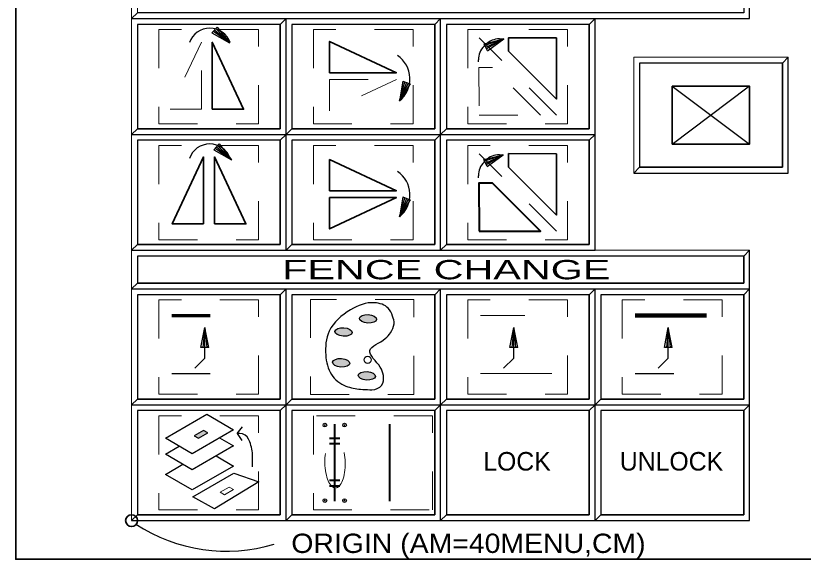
# Model space of a CAD drawing. Extents: x 95906.8 to 95923.6, y 90964.8 to 90972.8.
# Drawn here: x 95906.832 to 95908.871, y 90964.762 to 90966.169 of the extents above; entities that cross this region are included whole.
import ezdxf
from ezdxf.enums import TextEntityAlignment as Align

# ---------------------------------------------------------------- set-up
doc = ezdxf.new("R2010")
doc.units = 0
doc.header["$LTSCALE"] = 0.019
doc.header["$PDMODE"] = 32
doc.header["$PDSIZE"] = 0.0095
for name, pattern in [('DOT_DASHED', [7.7, 5, -1.2, 0.3, -1.2]), ('DOTTED', [1.5, 0.3, -1.2]), ('LONG_DASHED', [7.5, 6, -1.5]), ('MEDIUM_DASHED', [4.5, 3, -1.5])]:
    doc.linetypes.add(name, pattern=pattern)
for name, color, linetype, lineweight in [('11', 7, 'Continuous', 25), ('12', 7, 'Continuous', 25), ('16', 7, 'Continuous', 25), ('18', 7, 'Continuous', 25), ('2', 7, 'Continuous', 13), ('3', 7, 'Continuous', 25), ('6', 7, 'Continuous', 25), ('7', 7, 'Continuous', 35)]:
    doc.layers.add(name, color=color, linetype=linetype, lineweight=lineweight)

msp = doc.modelspace()

# ---------------------------------------------------------------- hatches: boundary and pattern name
at = {"layer": '6'}
h = msp.add_hatch(color=256, dxfattribs=at)
edge = h.paths.add_edge_path()
edge.add_ellipse((95907.7443, 90965.3842), major_axis=(-0.0223, 0.0015), ratio=0.490241, start_angle=0, end_angle=360)
h = msp.add_hatch(color=256, dxfattribs=at)
edge = h.paths.add_edge_path()
edge.add_ellipse((95907.6812, 90965.3504), major_axis=(-0.0223, 0.0015), ratio=0.490241, start_angle=0, end_angle=360)
h = msp.add_hatch(color=256, dxfattribs=at)
edge = h.paths.add_edge_path()
edge.add_ellipse((95907.6751, 90965.2705), major_axis=(-0.0223, 0.0015), ratio=0.490241, start_angle=0, end_angle=360)
h = msp.add_hatch(color=256, dxfattribs=at)
edge = h.paths.add_edge_path()
edge.add_ellipse((95907.7412, 90965.2366), major_axis=(-0.0223, 0.0015), ratio=0.490241, start_angle=0, end_angle=360)
msp.add_hatch(color=256, dxfattribs=at).paths.add_polyline_path([(95907.3058, 90965.0753), (95907.3293, 90965.0889), (95907.3181, 90965.0953), (95907.2946, 90965.0817)])

# ---------------------------------------------------------------- linework, layer by layer
at = {"layer": '11'}
for points in [[(95907.5473, 90965.8767), (95907.9173, 90965.8767), (95907.9173, 90966.1467), (95907.5473, 90966.1467)], [(95907.9473, 90965.8767), (95908.3173, 90965.8767), (95908.3173, 90966.1467), (95907.9473, 90966.1467)], [(95907.1473, 90965.5767), (95907.5173, 90965.5767), (95907.5173, 90965.8467), (95907.1473, 90965.8467)], [(95907.5473, 90965.5767), (95907.9173, 90965.5767), (95907.9173, 90965.8467), (95907.5473, 90965.8467)], [(95907.9473, 90965.5767), (95908.3173, 90965.5767), (95908.3173, 90965.8467), (95907.9473, 90965.8467)], [(95907.1473, 90965.1767), (95907.5173, 90965.1767), (95907.5173, 90965.4467), (95907.1473, 90965.4467)], [(95907.5473, 90965.1767), (95907.9173, 90965.1767), (95907.9173, 90965.4467), (95907.5473, 90965.4467)], [(95907.9473, 90965.1767), (95908.3173, 90965.1767), (95908.3173, 90965.4467), (95907.9473, 90965.4467)], [(95907.1473, 90964.8767), (95907.5173, 90964.8767), (95907.5173, 90965.1467), (95907.1473, 90965.1467)], [(95907.5473, 90964.8767), (95907.9173, 90964.8767), (95907.9173, 90965.1467), (95907.5473, 90965.1467)], [(95907.9473, 90964.8767), (95908.3173, 90964.8767), (95908.3173, 90965.1467), (95907.9473, 90965.1467)], [(95908.3473, 90964.8767), (95908.7173, 90964.8767), (95908.7173, 90965.1467), (95908.3473, 90965.1467)]]:
    msp.add_lwpolyline(points, close=True, dxfattribs=at)
at = {"layer": '12'}
for points in [[(95907.1473, 90965.8767), (95907.5173, 90965.8767), (95907.5173, 90966.1467), (95907.1473, 90966.1467)], [(95908.3473, 90965.1767), (95908.7173, 90965.1767), (95908.7173, 90965.4467), (95908.3473, 90965.4467)]]:
    msp.add_lwpolyline(points, close=True, dxfattribs=at)
at = {"layer": '16'}
msp.add_lwpolyline([(95908.4473, 90965.7767), (95908.8173, 90965.7767), (95908.8173, 90966.0467), (95908.4473, 90966.0467)], close=True, dxfattribs=at)
at = {"layer": '18'}
msp.add_lwpolyline([(95907.1473, 90965.4767), (95908.7173, 90965.4767), (95908.7173, 90965.5467), (95907.1473, 90965.5467)], close=True, dxfattribs=at)
at = {"layer": '2'}
for points in [[(95907.1323, 90966.2617), (95907.1323, 90966.1617), (95907.1473, 90966.1767), (95907.1473, 90966.2467), (95908.7173, 90966.2467), (95908.7323, 90966.2617)], [(95907.1323, 90966.1617), (95907.1323, 90965.8617), (95907.1473, 90965.8767), (95907.1473, 90966.1467), (95907.5173, 90966.1467), (95907.5323, 90966.1617)], [(95907.5323, 90966.1617), (95907.5323, 90965.8617), (95907.5473, 90965.8767), (95907.5473, 90966.1467), (95907.9173, 90966.1467), (95907.9323, 90966.1617)], [(95907.9323, 90966.1617), (95907.9323, 90965.8617), (95907.9473, 90965.8767), (95907.9473, 90966.1467), (95908.3173, 90966.1467), (95908.3323, 90966.1617)], [(95908.4323, 90966.0617), (95908.4323, 90965.7617), (95908.4473, 90965.7767), (95908.4473, 90966.0467), (95908.8173, 90966.0467), (95908.8323, 90966.0617)], [(95907.1323, 90965.8617), (95907.1323, 90965.5617), (95907.1473, 90965.5767), (95907.1473, 90965.8467), (95907.5173, 90965.8467), (95907.5323, 90965.8617)], [(95907.5323, 90965.8617), (95907.5323, 90965.5617), (95907.5473, 90965.5767), (95907.5473, 90965.8467), (95907.9173, 90965.8467), (95907.9323, 90965.8617)], [(95907.9323, 90965.8617), (95907.9323, 90965.5617), (95907.9473, 90965.5767), (95907.9473, 90965.8467), (95908.3173, 90965.8467), (95908.3323, 90965.8617)], [(95907.1323, 90965.5617), (95907.1323, 90965.4617), (95907.1473, 90965.4767), (95907.1473, 90965.5467), (95908.7173, 90965.5467), (95908.7323, 90965.5617)], [(95907.1323, 90965.4617), (95907.1323, 90965.1617), (95907.1473, 90965.1767), (95907.1473, 90965.4467), (95907.5173, 90965.4467), (95907.5323, 90965.4617)], [(95907.5323, 90965.4617), (95907.5323, 90965.1617), (95907.5473, 90965.1767), (95907.5473, 90965.4467), (95907.9173, 90965.4467), (95907.9323, 90965.4617)], [(95907.9323, 90965.4617), (95907.9323, 90965.1617), (95907.9473, 90965.1767), (95907.9473, 90965.4467), (95908.3173, 90965.4467), (95908.3323, 90965.4617)], [(95908.3323, 90965.4617), (95908.3323, 90965.1617), (95908.3473, 90965.1767), (95908.3473, 90965.4467), (95908.7173, 90965.4467), (95908.7323, 90965.4617)], [(95907.1323, 90965.1617), (95907.1323, 90964.8617), (95907.1473, 90964.8767), (95907.1473, 90965.1467), (95907.5173, 90965.1467), (95907.5323, 90965.1617)], [(95907.5323, 90965.1617), (95907.5323, 90964.8617), (95907.5473, 90964.8767), (95907.5473, 90965.1467), (95907.9173, 90965.1467), (95907.9323, 90965.1617)], [(95907.9323, 90965.1617), (95907.9323, 90964.8617), (95907.9473, 90964.8767), (95907.9473, 90965.1467), (95908.3173, 90965.1467), (95908.3323, 90965.1617)], [(95908.3323, 90965.1617), (95908.3323, 90964.8617), (95908.3473, 90964.8767), (95908.3473, 90965.1467), (95908.7173, 90965.1467), (95908.7323, 90965.1617)]]:
    msp.add_lwpolyline(points, close=True, dxfattribs=at)
at = {"layer": '3'}
for points in [[(95907.1323, 90966.1617), (95908.7323, 90966.1617), (95908.7323, 90966.2617), (95908.7173, 90966.2467), (95908.7173, 90966.1767), (95907.1473, 90966.1767)], [(95907.1323, 90965.8617), (95907.5323, 90965.8617), (95907.5323, 90966.1617), (95907.5173, 90966.1467), (95907.5173, 90965.8767), (95907.1473, 90965.8767)], [(95907.5323, 90965.8617), (95907.9323, 90965.8617), (95907.9323, 90966.1617), (95907.9173, 90966.1467), (95907.9173, 90965.8767), (95907.5473, 90965.8767)], [(95907.9323, 90965.8617), (95908.3323, 90965.8617), (95908.3323, 90966.1617), (95908.3173, 90966.1467), (95908.3173, 90965.8767), (95907.9473, 90965.8767)], [(95908.4323, 90965.7617), (95908.8323, 90965.7617), (95908.8323, 90966.0617), (95908.8173, 90966.0467), (95908.8173, 90965.7767), (95908.4473, 90965.7767)], [(95907.1323, 90965.5617), (95907.5323, 90965.5617), (95907.5323, 90965.8617), (95907.5173, 90965.8467), (95907.5173, 90965.5767), (95907.1473, 90965.5767)], [(95907.5323, 90965.5617), (95907.9323, 90965.5617), (95907.9323, 90965.8617), (95907.9173, 90965.8467), (95907.9173, 90965.5767), (95907.5473, 90965.5767)], [(95907.9323, 90965.5617), (95908.3323, 90965.5617), (95908.3323, 90965.8617), (95908.3173, 90965.8467), (95908.3173, 90965.5767), (95907.9473, 90965.5767)], [(95907.1323, 90965.4617), (95908.7323, 90965.4617), (95908.7323, 90965.5617), (95908.7173, 90965.5467), (95908.7173, 90965.4767), (95907.1473, 90965.4767)], [(95907.1323, 90965.1617), (95907.5323, 90965.1617), (95907.5323, 90965.4617), (95907.5173, 90965.4467), (95907.5173, 90965.1767), (95907.1473, 90965.1767)], [(95907.5323, 90965.1617), (95907.9323, 90965.1617), (95907.9323, 90965.4617), (95907.9173, 90965.4467), (95907.9173, 90965.1767), (95907.5473, 90965.1767)], [(95907.9323, 90965.1617), (95908.3323, 90965.1617), (95908.3323, 90965.4617), (95908.3173, 90965.4467), (95908.3173, 90965.1767), (95907.9473, 90965.1767)], [(95908.3323, 90965.1617), (95908.7323, 90965.1617), (95908.7323, 90965.4617), (95908.7173, 90965.4467), (95908.7173, 90965.1767), (95908.3473, 90965.1767)], [(95907.1323, 90964.8617), (95907.5323, 90964.8617), (95907.5323, 90965.1617), (95907.5173, 90965.1467), (95907.5173, 90964.8767), (95907.1473, 90964.8767)], [(95907.5323, 90964.8617), (95907.9323, 90964.8617), (95907.9323, 90965.1617), (95907.9173, 90965.1467), (95907.9173, 90964.8767), (95907.5473, 90964.8767)], [(95907.9323, 90964.8617), (95908.3323, 90964.8617), (95908.3323, 90965.1617), (95908.3173, 90965.1467), (95908.3173, 90964.8767), (95907.9473, 90964.8767)], [(95908.3323, 90964.8617), (95908.7323, 90964.8617), (95908.7323, 90965.1617), (95908.7173, 90965.1467), (95908.7173, 90964.8767), (95908.3473, 90964.8767)]]:
    msp.add_lwpolyline(points, close=True, dxfattribs=at)
at = {"layer": '6'}
for p, q in [((95907.3858, 90966.099), (95907.3439, 90966.1287)), ((95907.3469, 90966.1323), (95907.3858, 90966.099)), ((95908.0494, 90966.0876), (95908.0958, 90966.1092)), ((95908.0958, 90966.1092), (95908.0514, 90966.0832)), ((95908.0846, 90966.1094), (95908.0947, 90966.1094)), ((95908.0447, 90966.0902), (95908.0493, 90966.0948)), ((95908.0301, 90966.0495), (95908.0301, 90966.0549)), ((95907.8257, 90965.9486), (95907.84, 90965.998)), ((95907.8444, 90965.9962), (95907.8257, 90965.9486)), ((95908.5323, 90965.9867), (95908.7323, 90965.8367)), ((95908.5323, 90965.8367), (95908.7287, 90965.9852)), ((95907.3908, 90965.7961), (95907.3488, 90965.8258)), ((95907.3519, 90965.8294), (95907.3908, 90965.7961)), ((95908.0447, 90965.7902), (95908.0493, 90965.7948)), ((95908.0483, 90965.7878), (95908.0947, 90965.8094)), ((95908.0947, 90965.8094), (95908.0503, 90965.7834)), ((95908.0846, 90965.8094), (95908.0947, 90965.8094)), ((95908.0301, 90965.7495), (95908.0301, 90965.7549)), ((95907.8257, 90965.6486), (95907.84, 90965.698)), ((95907.8444, 90965.6962), (95907.8257, 90965.6486)), ((95907.3219, 90965.3105), (95907.3219, 90965.3617)), ((95907.3219, 90965.3617), (95907.3267, 90965.3105)), ((95908.1219, 90965.3105), (95908.1219, 90965.3617)), ((95908.1219, 90965.3617), (95908.1267, 90965.3105)), ((95908.5219, 90965.3105), (95908.5219, 90965.3617)), ((95908.5219, 90965.3617), (95908.5267, 90965.3105)), ((95907.4057, 90965.0875), (95907.4196, 90965.1044)), ((95907.4057, 90965.0875), (95907.418, 90965.0691)), ((95907.4124, 90965.0875), (95907.4057, 90965.0875)), ((95907.438, 90965.0659), (95907.4353, 90965.0725)), ((95907.4457, 90965.0014), (95907.4457, 90965.0275)), ((95907.4457, 90965.0014), (95907.4457, 90965.0275))]:
    msp.add_line(p, q, dxfattribs=at)
at = {"layer": '6', "linetype": 'MEDIUM_DASHED', "lineweight": 13}
for p, q in [((95908.2323, 90965.9117), (95908.0323, 90966.1117)), ((95908.2323, 90965.6117), (95908.0323, 90965.8117))]:
    msp.add_line(p, q, dxfattribs=at)
at = {"layer": '6', "linetype": 'DOT_DASHED', "lineweight": 70}
msp.add_line((95907.2361, 90965.393), (95907.4205, 90965.393), dxfattribs=at)
at = {"layer": '6', "linetype": 'LONG_DASHED', "lineweight": 13}
msp.add_line((95908.0361, 90965.393), (95908.2205, 90965.393), dxfattribs=at)
at = {"layer": '6', "lineweight": 158}
msp.add_line((95908.4361, 90965.393), (95908.6205, 90965.393), dxfattribs=at)
at = {"layer": '6', "linetype": 'DOTTED'}
msp.add_line((95907.2361, 90965.2424), (95907.4205, 90965.2424), dxfattribs=at)
at = {"layer": '6', "lineweight": 13}
msp.add_line((95908.0361, 90965.2424), (95908.2205, 90965.2424), dxfattribs=at)
at = {"layer": '6', "linetype": 'MEDIUM_DASHED'}
msp.add_line((95908.4361, 90965.2424), (95908.6205, 90965.2424), dxfattribs=at)
at = {"layer": '6', "lineweight": 40}
for p, q in [((95907.6573, 90965.1117), (95907.6573, 90964.9117)), ((95907.8003, 90965.1117), (95907.8003, 90964.9117)), ((95907.6451, 90965.0752), (95907.6713, 90965.0752)), ((95907.6451, 90965.0614), (95907.6713, 90965.0614)), ((95907.6451, 90964.9661), (95907.6713, 90964.9661)), ((95907.6451, 90964.9522), (95907.6713, 90964.9522))]:
    msp.add_line(p, q, dxfattribs=at)
at = {"layer": '6'}
for points in [[(95907.3403, 90966.1246), (95907.3536, 90966.14), (95907.3858, 90966.099)], [(95907.3403, 90966.1246), (95907.3858, 90966.099), (95907.3503, 90966.1361)], [(95908.0537, 90966.0784), (95908.045, 90966.0968), (95908.0958, 90966.1092)], [(95908.0537, 90966.0784), (95908.0958, 90966.1092), (95908.0472, 90966.0921)], [(95907.8349, 90966), (95907.8539, 90965.9925), (95907.8257, 90965.9486)], [(95907.8349, 90966), (95907.8257, 90965.9486), (95907.8491, 90965.9944)], [(95907.3452, 90965.8216), (95907.3586, 90965.8372), (95907.3908, 90965.7961)], [(95907.3452, 90965.8216), (95907.3908, 90965.7961), (95907.3551, 90965.8332)], [(95908.0526, 90965.7785), (95908.044, 90965.797), (95908.0947, 90965.8094)], [(95908.0526, 90965.7785), (95908.0947, 90965.8094), (95908.0462, 90965.7923)], [(95907.8349, 90965.7), (95907.8539, 90965.6925), (95907.8257, 90965.6486)], [(95907.8349, 90965.7), (95907.8257, 90965.6486), (95907.8491, 90965.6944)], [(95907.2956, 90965.2564), (95907.3219, 90965.2827), (95907.3219, 90965.3617)], [(95907.3321, 90965.3105), (95907.3117, 90965.3105), (95907.3219, 90965.3617)], [(95907.3321, 90965.3105), (95907.3219, 90965.3617), (95907.3169, 90965.3105)], [(95908.0956, 90965.2564), (95908.1219, 90965.2827), (95908.1219, 90965.3617)], [(95908.1321, 90965.3105), (95908.1117, 90965.3105), (95908.1219, 90965.3617)], [(95908.1321, 90965.3105), (95908.1219, 90965.3617), (95908.1169, 90965.3105)], [(95908.4956, 90965.2564), (95908.5219, 90965.2827), (95908.5219, 90965.3617)], [(95908.5321, 90965.3105), (95908.5117, 90965.3105), (95908.5219, 90965.3617)], [(95908.5321, 90965.3105), (95908.5219, 90965.3617), (95908.5169, 90965.3105)], [(95907.3602, 90965.0763), (95907.3965, 90965.0552), (95907.2895, 90964.9934), (95907.2197, 90965.0337), (95907.2554, 90965.0543)], [(95907.3511, 90965.0292), (95907.3965, 90965.0029), (95907.2895, 90964.9411), (95907.2197, 90964.9814), (95907.265, 90965.0076)]]:
    msp.add_lwpolyline(points, dxfattribs=at)
at = {"layer": '6', "linetype": 'DOTTED', "lineweight": 13}
for points in [[(95907.2029, 90965.8893), (95907.4611, 90965.8893), (95907.4611, 90966.1332), (95907.2029, 90966.1332)], [(95907.6029, 90965.8893), (95907.8611, 90965.8893), (95907.8611, 90966.1332), (95907.6029, 90966.1332)], [(95908.0029, 90965.8893), (95908.2611, 90965.8893), (95908.2611, 90966.1332), (95908.0029, 90966.1332)], [(95907.2029, 90965.5893), (95907.4611, 90965.5893), (95907.4611, 90965.8332), (95907.2029, 90965.8332)], [(95907.6029, 90965.5893), (95907.8611, 90965.5893), (95907.8611, 90965.8332), (95907.6029, 90965.8332)], [(95908.0029, 90965.5893), (95908.2611, 90965.5893), (95908.2611, 90965.8332), (95908.0029, 90965.8332)], [(95907.2029, 90965.1893), (95907.4611, 90965.1893), (95907.4611, 90965.4332), (95907.2029, 90965.4332)], [(95907.8627, 90965.4347), (95907.5955, 90965.4347), (95907.5955, 90965.1883), (95907.8627, 90965.1883)], [(95908.0029, 90965.1893), (95908.2611, 90965.1893), (95908.2611, 90965.4332), (95908.0029, 90965.4332)], [(95908.4029, 90965.1893), (95908.6611, 90965.1893), (95908.6611, 90965.4332), (95908.4029, 90965.4332)], [(95907.2029, 90964.8893), (95907.4611, 90964.8893), (95907.4611, 90965.1332), (95907.2029, 90965.1332)], [(95907.6029, 90964.8893), (95907.9111, 90964.8893), (95907.9111, 90965.1332), (95907.6029, 90965.1332)]]:
    msp.add_lwpolyline(points, close=True, dxfattribs=at)
at = {"layer": '6', "linetype": 'MEDIUM_DASHED', "lineweight": 13}
for points in [[(95907.3129, 90965.9271), (95907.3129, 90966.1005), (95907.2318, 90965.9271)], [(95908.0323, 90965.9117), (95908.1909, 90965.9117), (95908.067, 90966.0356), (95908.0317, 90966.0356)], [(95907.6447, 90966.004), (95907.818, 90966.004), (95907.6447, 90965.9228)], [(95907.3724, 90964.9288), (95907.3959, 90964.9424), (95907.3847, 90964.9488), (95907.3612, 90964.9352)]]:
    msp.add_lwpolyline(points, close=True, dxfattribs=at)
at = {"layer": '6', "lineweight": 35}
for points in [[(95907.3412, 90965.9271), (95907.3412, 90966.1005), (95907.4224, 90965.9271)], [(95907.6447, 90966.0216), (95907.818, 90966.0216), (95907.6447, 90966.1027)], [(95908.2324, 90966.1118), (95908.2324, 90965.9532), (95908.1085, 90966.0771), (95908.1085, 90966.1124)], [(95908.5323, 90965.8367), (95908.7323, 90965.8367), (95908.7323, 90965.9867), (95908.5323, 90965.9867)], [(95908.2324, 90965.8118), (95908.2324, 90965.6532), (95908.1085, 90965.7771), (95908.1085, 90965.8124)], [(95907.3187, 90965.6303), (95907.3187, 90965.8037), (95907.2376, 90965.6303)], [(95907.347, 90965.6303), (95907.347, 90965.8037), (95907.4282, 90965.6303)], [(95907.6447, 90965.7158), (95907.818, 90965.7158), (95907.6447, 90965.7969)], [(95907.6447, 90965.6982), (95907.818, 90965.6982), (95907.6447, 90965.617)]]:
    msp.add_lwpolyline(points, close=True, dxfattribs=at)
at = {"layer": '6', "lineweight": 40}
msp.add_lwpolyline([(95908.0323, 90965.6117), (95908.1909, 90965.6117), (95908.067, 90965.7356), (95908.0317, 90965.7356)], close=True, dxfattribs=at)
at = {"layer": '6'}
for points in [[(95907.2197, 90965.0752), (95907.3267, 90965.137), (95907.3965, 90965.0967), (95907.2895, 90965.0349)], [(95907.3058, 90965.0753), (95907.3293, 90965.0889), (95907.3181, 90965.0953), (95907.2946, 90965.0817)], [(95907.2904, 90964.923), (95907.3974, 90964.9848), (95907.4617, 90964.9625), (95907.3468, 90964.8921)]]:
    msp.add_lwpolyline(points, close=True, dxfattribs=at)
msp.add_circle((95907.7435, 90965.2782), 0.00934, dxfattribs=at)
for centre, radius, start, end in [((95907.3347, 90966.081), 0.0561, 19.3993, 160.6007), ((95908.0846, 90966.0594), 0.05, 90, 135), ((95908.0801, 90966.0549), 0.05, 135, 180), ((95907.7804, 90966.0054), 0.0727, 308.5635, 56.4113), ((95907.3347, 90965.781), 0.0561, 19.3993, 160.6007), ((95908.0846, 90965.7594), 0.05, 90, 135), ((95908.0801, 90965.7549), 0.05, 135, 180), ((95907.7804, 90965.7054), 0.0727, 308.5635, 56.4113), ((95907.4124, 90965.0625), 0.025, 23.5654, 90), ((95907.3457, 90965.0275), 0.1, 0, 22.5992)]:
    msp.add_arc(centre, radius, start, end, dxfattribs=at)
for centre in [(95907.7443, 90965.3842), (95907.6812, 90965.3504), (95907.6751, 90965.2705), (95907.7412, 90965.2366)]:
    msp.add_ellipse(centre, major_axis=(-0.0223, 0.0015), ratio=0.490241, dxfattribs=at)
at = {"layer": '6', "linetype": 'MEDIUM_DASHED', "lineweight": 13}
msp.add_ellipse((95907.6589, 90965.0115), major_axis=(0.0015, -0.0654), ratio=0.400869, dxfattribs=at)
at = {"layer": '6'}
msp.add_spline([(95907.749, 90965.2007), (95907.7252, 90965.2021), (95907.6874, 90965.2101), (95907.6496, 90965.2402), (95907.6349, 90965.2905), (95907.6439, 90965.3524), (95907.6993, 90965.4078), (95907.7611, 90965.426), (95907.7969, 90965.4116), (95907.8079, 90965.3915), (95907.8119, 90965.3711), (95907.8026, 90965.3484), (95907.7892, 90965.333), (95907.7493, 90965.3022), (95907.7761, 90965.259), (95907.7842, 90965.2379), (95907.7795, 90965.2118), (95907.7547, 90965.2007), (95907.749, 90965.2007)], degree=3, dxfattribs=at)
for p in [(95907.6328, 90965.109), (95907.6836, 90965.109), (95907.6328, 90964.9138), (95907.6836, 90964.9138)]:
    msp.add_point(p, dxfattribs=at)
at = {"layer": '7'}
msp.add_lwpolyline([(95906.8323, 90972.7617), (95918.8323, 90972.7617), (95918.8323, 90964.7617), (95906.8323, 90964.7617)], close=True, dxfattribs=at)
msp.add_circle((95907.1323, 90964.8617), 0.0154, dxfattribs=at)
at = {"layer": '7', "lineweight": 25}
msp.add_arc((95907.3775, 90965.209), 0.4264, 236.6831, 286.8865, dxfattribs=at)

# ---------------------------------------------------------------- texts
at = {"layer": '6'}
for s, p in [('LOCK', (95908.1301, 90964.9914)), ('UNLOCK', (95908.5302, 90964.9914))]:
    msp.add_text(s, height=0.048, dxfattribs=at).set_placement(p, align=Align.CENTER)
at = {"layer": '7'}
for s, height, width, p in [('      FENCE CHANGE     ', 0.04999, 1.6, (95907.9322, 90965.4867)), ('ORIGIN (AM=40MENU,CM)', 0.05, 1.1, (95908.0045, 90964.778))]:
    msp.add_text(s, height=height, dxfattribs=dict(at, width=width)).set_placement(p, align=Align.CENTER)

doc.saveas('drawing.dxf')
